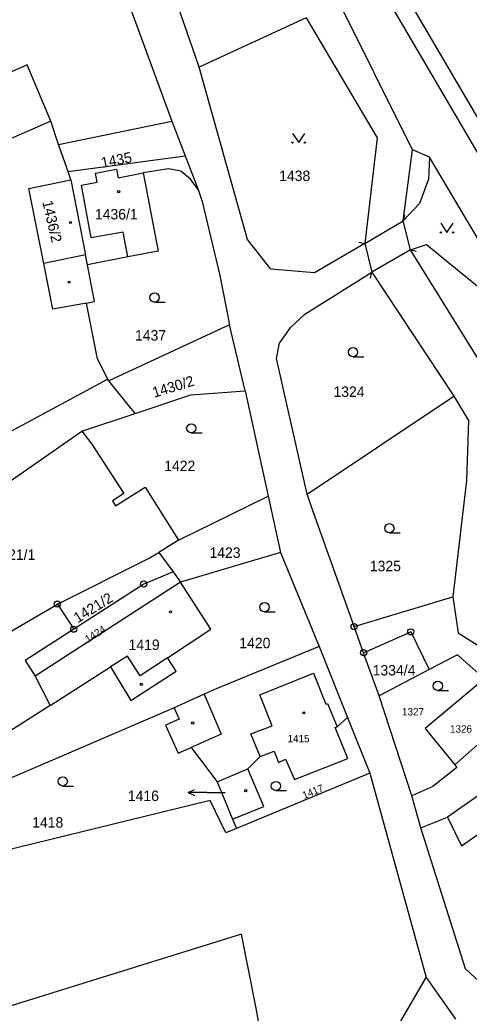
# Model space of a CAD drawing. Extents: x -504988 to -494607, y -1123820 to -1114018.
# Drawn here: x -498111.8 to -498038.7, y -1119099.6 to -1118938 of the extents above; entities that cross this region are included whole.
import ezdxf

# ---------------------------------------------------------------- set-up
doc = ezdxf.new("R2010")
doc.units = 0
for name, color, linetype in [('Hranice parcel', 7, 'Continuous'), ('Parcelní čísla', 7, 'Continuous'), ('Pop  PČ popisy', 7, 'Continuous'), ('Vnitřní kresba', 7, 'Continuous'), ('Značky bodu BP', 7, 'Continuous'), ('Značky budov', 7, 'Continuous'), ('Značky kultur', 7, 'Continuous')]:
    doc.layers.add(name, color=color, linetype=linetype)

msp = doc.modelspace()

# ---------------------------------------------------------------- linework, layer by layer
at = {"layer": 'Hranice parcel'}
for p, q in [((-498065.23, -1118937.68), (-498082.61, -1118945.71)), ((-498105.52, -1118958.3), (-498087.06, -1118954.5)), ((-498087.06, -1118954.5), (-498084.9, -1118960.12)), ((-498103.94, -1118962.68), (-498105.52, -1118958.3)), ((-498103.94, -1118962.68), (-498084.9, -1118960.12)), ((-498084.9, -1118960.12), (-498082.79, -1118965.6)), ((-498049.45, -1118970.72), (-498047.91, -1118959.14)), ((-498103.48, -1118964.03), (-498103.94, -1118962.68)), ((-498103.48, -1118964.03), (-498101.1, -1118976.25)), ((-498048.26, -1118975.43), (-498049.45, -1118970.72)), ((-498055.67, -1118974.42), (-498054.53, -1118979.07)), ((-498100.79, -1118977.85), (-498101.1, -1118976.25)), ((-498033.84, -1118998.69), (-498048.26, -1118975.43)), ((-498054.53, -1118979.07), (-498041.21, -1118999.26)), ((-498077.7, -1118987.65), (-498097.29, -1118996.73)), ((-498075.15, -1118998.35), (-498077.7, -1118987.65)), ((-498097.29, -1118996.73), (-498097.5, -1118996.47)), ((-498093.01, -1119002.03), (-498097.29, -1118996.73)), ((-498075.15, -1118998.35), (-498071.39, -1119015.51)), ((-498065.04, -1119015.19), (-498041.21, -1118999.26)), ((-498101.69, -1119004.92), (-498093.01, -1119002.03)), ((-498085.97, -1119022.64), (-498071.39, -1119015.51)), ((-498071.39, -1119015.51), (-498069.41, -1119024.68)), ((-498085.97, -1119022.64), (-498089.21, -1119024.64)), ((-498089.21, -1119024.64), (-498086.84, -1119027.8)), ((-498069.41, -1119024.68), (-498085.67, -1119029.49)), ((-498069.41, -1119024.68), (-498063.13, -1119039.97)), ((-498086.84, -1119027.8), (-498085.67, -1119029.49)), ((-498085.67, -1119029.49), (-498109.31, -1119044.76)), ((-498057.43, -1119036.72), (-498041.37, -1119031.85)), ((-498129.43, -1119047), (-498105.68, -1119033.05)), ((-498105.68, -1119033.05), (-498103.02, -1119037.14)), ((-498055.88, -1119040.97), (-498057.43, -1119036.72)), ((-498063.13, -1119039.97), (-498058.51, -1119051.48)), ((-498053.33, -1119047.99), (-498055.88, -1119040.97)), ((-498045.22, -1119043.71), (-498053.33, -1119047.99)), ((-498109.31, -1119044.76), (-498106.84, -1119049.53)), ((-498048.06, -1119064.27), (-498053.33, -1119047.99)), ((-498086.7, -1119049.92), (-498124.19, -1119066.08)), ((-498058.51, -1119051.48), (-498054.87, -1119060.58)), ((-498079.72, -1119061.99), (-498074.69, -1119059.85)), ((-498054.87, -1119060.58), (-498076.58, -1119069.54)), ((-498054.87, -1119060.58), (-498045.7, -1119093.78)), ((-498079.72, -1119061.99), (-498077.21, -1119068.04)), ((-498046.56, -1119069.43), (-498048.06, -1119064.27)), ((-498077.21, -1119068.04), (-498076.58, -1119069.54)), ((-498045.7, -1119093.78), (-498040.95, -1119100.58))]:
    msp.add_line(p, q, dxfattribs=at)
for points in [[(-497984.84, -1119039.44), (-497996.67, -1119026.04), (-498011.01, -1119004.52), (-498055.26, -1118929.03), (-498085.44, -1118876.75), (-498105.99, -1118841.88), (-498108.75, -1118836.88)], [(-498047.91, -1118959.14), (-498060.59, -1118933.75), (-498069.37, -1118918.06), (-498072.75, -1118911.99), (-498103.78, -1118859.7), (-498110.93, -1118848.54)], [(-498073.95, -1118891.76), (-498052.77, -1118927.65), (-498035.88, -1118956.45)], [(-498082.61, -1118945.71), (-498090.05, -1118924.19), (-498094.34, -1118909.35)], [(-498095.99, -1118930.05), (-498095.7, -1118930.99), (-498087.06, -1118954.5)], [(-498065.23, -1118937.68), (-498053.68, -1118957.19), (-498055.67, -1118974.42)], [(-498105.52, -1118958.3), (-498106.74, -1118954.51), (-498110.61, -1118945.36), (-498115.72, -1118947.6), (-498117.42, -1118943.64)], [(-498055.67, -1118974.42), (-498063.85, -1118979.19), (-498070.95, -1118978.56), (-498074.78, -1118973.77), (-498082.61, -1118945.71)], [(-498026.43, -1118994.68), (-498025.28, -1118994.06), (-498028.29, -1118988.76), (-498045.19, -1118960.37), (-498047.91, -1118959.14)], [(-498082.79, -1118965.6), (-498084.01, -1118963.94), (-498085.59, -1118962.62), (-498087.62, -1118962.28), (-498091.74, -1118962.92), (-498089.28, -1118975.67), (-498094.22, -1118976.59), (-498100.79, -1118977.85)], [(-498101.1, -1118976.25), (-498107.87, -1118977.68), (-498110.35, -1118965.43), (-498103.48, -1118964.03)], [(-498082.79, -1118965.6), (-498082.15, -1118967.58), (-498079.29, -1118979.61), (-498077.7, -1118987.65)], [(-498097.5, -1118996.47), (-498099.16, -1118993.17), (-498100.95, -1118984.09), (-498099.63, -1118983.85), (-498100.79, -1118977.85)], [(-498065.04, -1119015.19), (-498070.03, -1118993.09), (-498069.54, -1118990.64), (-498067.73, -1118988.02), (-498065.43, -1118985.9), (-498054.53, -1118979.07)], [(-498097.5, -1118996.47), (-498119.06, -1119008.07), (-498123.46, -1119010.4)], [(-498093.01, -1119002.03), (-498083.97, -1118999.01), (-498075.15, -1118998.35)], [(-498041.21, -1118999.26), (-498038.81, -1119003.19), (-498039.16, -1119012.93), (-498041.37, -1119031.85)], [(-498135.48, -1119026.94), (-498126.65, -1119022.26), (-498101.69, -1119004.92)], [(-498101.69, -1119004.92), (-498100.06, -1119007.05), (-498094.87, -1119015.09), (-498096.73, -1119016.28), (-498096.23, -1119017.08), (-498091.42, -1119014.02), (-498085.97, -1119022.64)], [(-498057.43, -1119036.72), (-498064.38, -1119017.26), (-498065.04, -1119015.19)], [(-498105.68, -1119033.05), (-498090.88, -1119025.66), (-498089.21, -1119024.64)], [(-498086.84, -1119027.8), (-498091.65, -1119029.79), (-498103.02, -1119037.14)], [(-498106.84, -1119049.53), (-498097.06, -1119043.29), (-498093.72, -1119048.75), (-498086.36, -1119043.98), (-498087.8, -1119041.78), (-498080.75, -1119037.15), (-498085.67, -1119029.49)], [(-498041.37, -1119031.85), (-498040.53, -1119037.75), (-498029.11, -1119044.97), (-498017.68, -1119049.12), (-498018.58, -1119050.89)], [(-498103.02, -1119037.14), (-498110.93, -1119042.25), (-498109.31, -1119044.76)], [(-498055.88, -1119040.97), (-498048.22, -1119037.57), (-498045.22, -1119043.71)], [(-498063.13, -1119039.97), (-498079.87, -1119046.86), (-498081.82, -1119047.73), (-498086.7, -1119049.92)], [(-498036.2, -1119045.22), (-498040.63, -1119041.29), (-498045.22, -1119043.71)], [(-498036.2, -1119045.22), (-498045.89, -1119053.32), (-498041.05, -1119059.21), (-498040.71, -1119059.62), (-498044.63, -1119062.73), (-498048.06, -1119064.27)], [(-498106.84, -1119049.53), (-498114.59, -1119054.49), (-498123.54, -1119059.82)], [(-498086.7, -1119049.92), (-498085.88, -1119051.75), (-498088.09, -1119052.74), (-498086.05, -1119057.3), (-498083.91, -1119056.36), (-498079.72, -1119061.99)], [(-498074.69, -1119059.85), (-498072.68, -1119057.85), (-498070.43, -1119056.98), (-498069.7, -1119058.8), (-498068.59, -1119058.29), (-498067.15, -1119061.61), (-498058.45, -1119058.19), (-498060.49, -1119053.14), (-498060.21, -1119053.03), (-498058.51, -1119051.48)], [(-498046.56, -1119069.43), (-498042.25, -1119067.73), (-498039.98, -1119072.38), (-498032.09, -1119066.92), (-498021.23, -1119059.4), (-498018.13, -1119057.26), (-498021.28, -1119052.9)], [(-498077.21, -1119068.04), (-498072.12, -1119065.99), (-498074.69, -1119059.85)], [(-498076.58, -1119069.54), (-498078.27, -1119070.24), (-498080.81, -1119065), (-498119.89, -1119074.55), (-498123.76, -1119075.36), (-498188.38, -1119091.18)], [(-498030.53, -1119100.54), (-498039.34, -1119092.4), (-498046.56, -1119069.43)], [(-498071.47, -1119109.28), (-498071.55, -1119108.79), (-498073.34, -1119098.8), (-498075.74, -1119086.77), (-498132.3, -1119104.31), (-498131.11, -1119113.44)], [(-498071.47, -1119109.28), (-498054.58, -1119104.39), (-498050.79, -1119102.58), (-498045.7, -1119093.78)]]:
    msp.add_lwpolyline(points, dxfattribs=at)
at = {"layer": 'Pop  PČ popisy'}
for p, q in [((-498084.4, -1119063.69), (-498083.4, -1119063.19)), ((-498081.4, -1119063.69), (-498084.4, -1119063.69)), ((-498084.4, -1119063.69), (-498083.4, -1119064.19)), ((-498081.4, -1119063.69), (-498078.4, -1119063.69))]:
    msp.add_line(p, q, dxfattribs=at)
at = {"layer": 'Vnitřní kresba'}
for p, q in [((-498106.74, -1118954.51), (-498136.86, -1118967.52)), ((-498045.19, -1118960.37), (-498045.33, -1118963.94)), ((-498099.49, -1118962.96), (-498096.05, -1118962.32)), ((-498099.2, -1118964.4), (-498099.49, -1118962.96)), ((-498096.05, -1118962.32), (-498095.78, -1118963.72)), ((-498095.78, -1118963.72), (-498091.74, -1118962.92)), ((-498101.78, -1118964.91), (-498099.2, -1118964.4)), ((-498100.21, -1118973.49), (-498101.78, -1118964.91)), ((-498045.33, -1118963.94), (-498046.78, -1118967.87)), ((-498046.78, -1118967.87), (-498049.45, -1118970.72)), ((-498049.21, -1118969.75), (-498049.45, -1118970.72)), ((-498055.67, -1118974.42), (-498049.45, -1118970.72)), ((-498094.96, -1118972.53), (-498100.21, -1118973.49)), ((-498094.22, -1118976.59), (-498094.96, -1118972.53)), ((-498056.64, -1118974.18), (-498055.67, -1118974.42)), ((-498048.26, -1118975.43), (-498045.65, -1118974.59)), ((-498045.65, -1118974.59), (-498028.29, -1118988.76)), ((-498048.26, -1118975.43), (-498054.53, -1118979.07)), ((-498047.29, -1118975.69), (-498048.26, -1118975.43)), ((-498106.4, -1118985.08), (-498107.87, -1118977.68)), ((-498054.79, -1118980.04), (-498054.53, -1118979.07)), ((-498100.95, -1118984.09), (-498106.4, -1118985.08)), ((-498094.28, -1119041.51), (-498097.06, -1119043.29)), ((-498092.24, -1119044.7), (-498094.28, -1119041.51)), ((-498087.8, -1119041.78), (-498092.24, -1119044.7)), ((-498072.75, -1119047.84), (-498064.06, -1119044.27)), ((-498064.06, -1119044.27), (-498062.02, -1119049.34)), ((-498081.82, -1119047.73), (-498079.04, -1119054.22)), ((-498070.73, -1119052.86), (-498072.75, -1119047.84)), ((-498062.02, -1119049.34), (-498061.74, -1119049.23)), ((-498061.74, -1119049.23), (-498060.21, -1119053.03)), ((-498031.55, -1119050.78), (-498041.05, -1119059.21)), ((-498074.22, -1119054.17), (-498070.73, -1119052.86)), ((-498079.04, -1119054.22), (-498083.91, -1119056.36)), ((-498072.68, -1119057.85), (-498074.22, -1119054.17)), ((-498034.96, -1119062.58), (-498042.25, -1119067.73))]:
    msp.add_line(p, q, dxfattribs=at)
at = {"layer": 'Značky bodu BP'}
for centre, radius in [((-498091.65, -1119029.79), 0.5), ((-498091.65, -1119029.79), 0.0303), ((-498105.68, -1119033.05), 0.5), ((-498105.68, -1119033.05), 0.0303), ((-498103.02, -1119037.14), 0.5), ((-498103.02, -1119037.14), 0.0303), ((-498057.43, -1119036.72), 0.5), ((-498057.43, -1119036.72), 0.0303), ((-498048.22, -1119037.57), 0.5), ((-498048.22, -1119037.57), 0.0303), ((-498055.88, -1119040.97), 0.5), ((-498055.88, -1119040.97), 0.0303)]:
    msp.add_circle(centre, radius, dxfattribs=at)
at = {"layer": 'Značky budov'}
for centre in [(-498095.72, -1118965.98), (-498103.55, -1118970.99), (-498103.77, -1118980.7), (-498087.29, -1119034.31), (-498092.04, -1119046.11), (-498065.6, -1119050.74), (-498083.68, -1119052.41), (-498075.05, -1119063.4)]:
    msp.add_circle(centre, 0.175, dxfattribs=at)
at = {"layer": 'Značky kultur'}
for p, q in [((-498089.88, -1118983.94), (-498088.13, -1118983.94)), ((-498057.61, -1118992.84), (-498055.86, -1118992.84)), ((-498083.91, -1119005.21), (-498082.16, -1119005.21)), ((-498051.69, -1119021.47), (-498049.94, -1119021.47)), ((-498072.01, -1119034.31), (-498070.26, -1119034.31)), ((-498043.81, -1119047.11), (-498042.06, -1119047.11)), ((-498104.81, -1119062.65), (-498103.06, -1119062.65)), ((-498070.15, -1119063.4), (-498068.4, -1119063.4))]:
    msp.add_line(p, q, dxfattribs=at)
for points in [[(-498067.44, -1118956.49), (-498066.44, -1118957.99), (-498065.44, -1118956.49)], [(-498043.33, -1118971.1), (-498042.33, -1118972.6), (-498041.33, -1118971.1)]]:
    msp.add_lwpolyline(points, dxfattribs=at)
for centre, radius in [((-498067.44, -1118957.99), 0.1), ((-498065.44, -1118957.99), 0.1), ((-498043.33, -1118972.6), 0.1), ((-498041.33, -1118972.6), 0.1), ((-498089.88, -1118983.19), 0.75), ((-498057.61, -1118992.09), 0.75), ((-498083.91, -1119004.46), 0.75), ((-498051.69, -1119020.72), 0.75), ((-498072.01, -1119033.56), 0.75), ((-498043.81, -1119046.36), 0.75), ((-498104.81, -1119061.9), 0.75), ((-498070.15, -1119062.65), 0.75)]:
    msp.add_circle(centre, radius, dxfattribs=at)

# ---------------------------------------------------------------- texts
at = {"layer": 'Parcelní čísla'}
for s, height, rotation, p in [('1435', 1.7, 11, (-498098.41, -1118962.12)), ('1436/2', 1.7, 283, (-498108.14, -1118967.61)), ('1430/2', 1.7, 17, (-498089.94, -1118999.5)), ('1421/2', 1.7, 32, (-498102.37, -1119036.19)), ('1424', 1.2, 32, (-498100.73, -1119039.38)), ('1417', 1.2, 22, (-498065.57, -1119064.78))]:
    msp.add_text(s, height=height, rotation=rotation, dxfattribs=at).set_placement(p)
for s, height, p in [('1438', 1.7, (-498069.62, -1118964.24)), ('1436/1', 1.7, (-498099.58, -1118970.49)), ('1437', 1.7, (-498093.06, -1118990.19)), ('1324', 1.7, (-498060.79, -1118999.36)), ('1422', 1.7, (-498088.31, -1119011.43)), ('1421/1', 1.7, (-498116.22, -1119025.87)), ('1423', 1.7, (-498080.95, -1119025.54)), ('1325', 1.7, (-498054.87, -1119027.72)), ('1419', 1.7, (-498094.11, -1119040.52)), ('1420', 1.7, (-498076.1, -1119040.24)), ('1334/4', 1.7, (-498054.41, -1119044.67)), ('1327', 1.2, (-498049.64, -1119051.17)), ('1326', 1.2, (-498041.83, -1119053.97)), ('1415', 1.2, (-498068.25, -1119055.53)), ('1416', 1.7, (-498094.23, -1119065.1)), ('1418', 1.7, (-498109.78, -1119069.42))]:
    msp.add_text(s, height=height, dxfattribs=at).set_placement(p)

doc.saveas('drawing.dxf')
